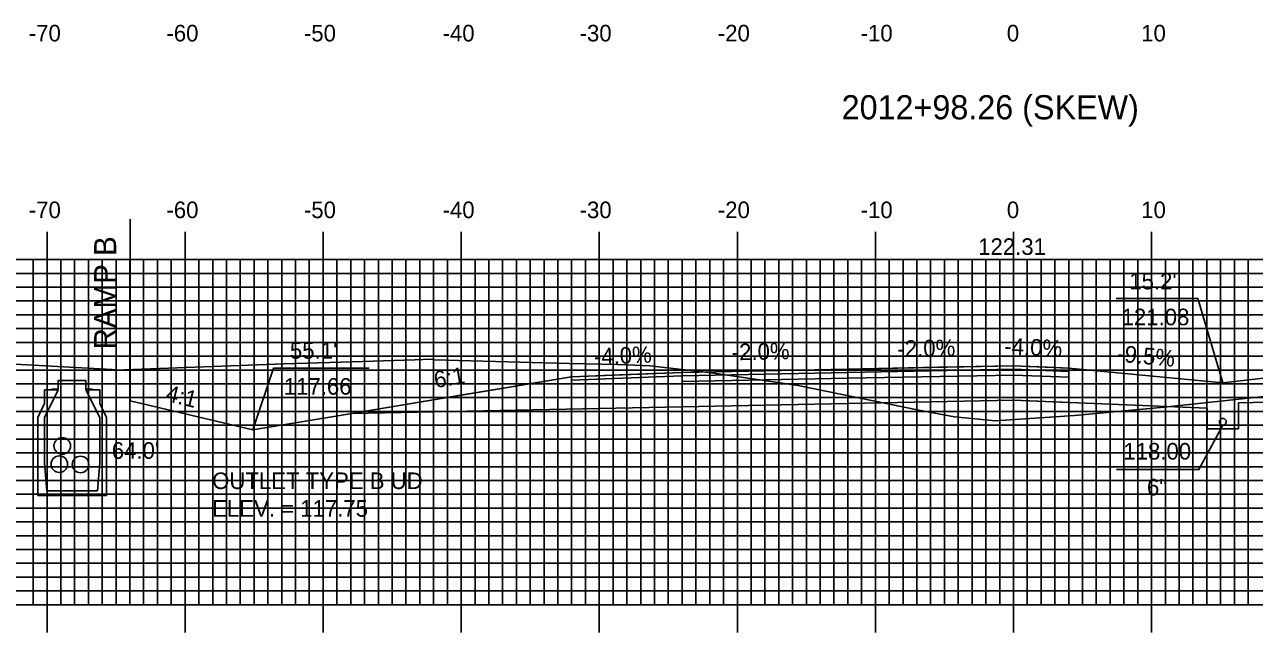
# Model space of a CAD drawing. Extents: x 853894 to 854237, y 366605 to 366825.
# Drawn here: x 853987.9 to 854077, y 366706.1 to 366750.1 of the extents above; entities that cross this region are included whole.
import ezdxf

# ---------------------------------------------------------------- set-up
doc = ezdxf.new("R2010")
doc.units = 0
for name, color, linetype in [('ANNOTATION', 7, 'Continuous'), ('D_Roadway_Centerline', 7, 'Continuous'), ('D_Roadway_Centerline_Text', 7, 'Continuous'), ('D_Roadway_Edge_Shoulder', 7, 'Continuous'), ('D_Roadway_Edge_TW', 7, 'Continuous'), ('D_Roadway_Pavement', 7, 'Continuous'), ('D_Roadway_SubGrade', 7, 'Continuous'), ('D_Text_Standard', 7, 'Continuous'), ('H_V ANNOTATION', 7, 'Continuous'), ('M_Roadway_Centerline', 7, 'Continuous'), ('MAJOR', 7, 'Continuous'), ('MINOR', 7, 'Continuous'), ('PDRAIN', 7, 'Continuous'), ('S_Drainage_CB', 7, 'Continuous'), ('S_Drainage_Invert', 7, 'Continuous'), ('S_Roadway_Centerline', 7, 'Continuous')]:
    doc.layers.add(name, color=color, linetype=linetype)

msp = doc.modelspace()

# ---------------------------------------------------------------- linework, layer by layer
at = {"layer": 'ANNOTATION'}
for points in [[(854066.975, 366730.223), (854072.876, 366730.223), (854074.694, 366724.138)], [(854012.87, 366725.196), (854005.941, 366725.196), (854004.439, 366720.713)], [(854066.993, 366717.845), (854072.964, 366717.845), (854074.694, 366721.055)]]:
    msp.add_lwpolyline(points, dxfattribs=at)
at = {"layer": 'D_Roadway_Centerline'}
for p, q in [((854059.53, 366722.861), (854073.569, 366722.3)), ((854084.707, 366722.859), (854075.819, 366722.677))]:
    msp.add_line(p, q, dxfattribs=at)
for points in [[(854010.439, 366721.713), (854010.445, 366721.714), (854020.081, 366723.32), (854027.53, 366724.561), (854027.532, 366724.561), (854031.021, 366724.701), (854035.528, 366724.881), (854035.53, 366724.881), (854047.525, 366725.121), (854047.53, 366725.121), (854054.093, 366725.252), (854059.53, 366725.361), (854062.579, 366725.239), (854063.53, 366725.201), (854063.531, 366725.201), (854074.694, 366724.138)], [(854063.53, 366725.201), (854074.694, 366724.138)], [(854074.694, 366724.138), (854077.41, 366724.448), (854084.707, 366725.279)]]:
    msp.add_lwpolyline(points, dxfattribs=at)
at = {"layer": 'D_Roadway_Edge_Shoulder'}
for points in [[(854035.53, 366724.881), (854027.53, 366724.561), (854027.53, 366724.311), (854035.53, 366724.631)], [(854059.53, 366725.361), (854063.53, 366725.201), (854063.53, 366724.951), (854059.53, 366725.111)]]:
    msp.add_lwpolyline(points, close=True, dxfattribs=at)
at = {"layer": 'D_Roadway_Edge_TW'}
for points in [[(854047.53, 366725.121), (854035.53, 366724.881), (854035.53, 366724.631), (854047.53, 366724.871)], [(854059.53, 366725.361), (854047.53, 366725.121), (854047.53, 366724.871), (854059.53, 366725.111)]]:
    msp.add_lwpolyline(points, close=True, dxfattribs=at)
at = {"layer": 'D_Roadway_Pavement'}
for points in [[(854047.53, 366724.871), (854035.53, 366724.631), (854035.53, 366724.214), (854047.53, 366724.454)], [(854059.53, 366725.111), (854047.53, 366724.871), (854047.53, 366724.454), (854059.53, 366724.694)], [(854059.53, 366725.111), (854063.53, 366724.951), (854063.53, 366724.534), (854059.53, 366724.694)], [(854035.53, 366724.631), (854035.53, 366724.214), (854035.53, 366724.214)]]:
    msp.add_lwpolyline(points, close=True, dxfattribs=at)
msp.add_lwpolyline([(854047.53, 366724.871), (854047.53, 366724.454)], dxfattribs=at)
at = {"layer": 'D_Roadway_SubGrade'}
msp.add_line((853995.55, 366735.973), (853995.55, 366722.827), dxfattribs=at)
for points in [[(854059.53, 366724.694), (854063.53, 366724.534), (854063.53, 366724.951), (854063.53, 366725.201), (854063.53, 366722.701), (854059.53, 366722.861)], [(854035.53, 366724.214), (854035.53, 366724.214), (854035.53, 366724.631), (854027.53, 366724.311), (854027.53, 366724.561), (854011.576, 366721.902), (854035.53, 366722.381)], [(854047.53, 366724.454), (854035.53, 366724.214), (854035.53, 366722.381), (854047.53, 366722.621)], [(854059.53, 366724.694), (854047.53, 366724.454), (854047.53, 366722.621), (854059.53, 366722.861)]]:
    msp.add_lwpolyline(points, close=True, dxfattribs=at)
msp.add_lwpolyline([(854010.439, 366721.713), (854004.439, 366720.713), (853995.55, 366722.827)], dxfattribs=at)
at = {"layer": 'MAJOR'}
for p, q in [((853989.53, 366735.059), (853989.53, 366733.055)), ((853999.53, 366735.059), (853999.53, 366733.055)), ((854009.53, 366735.059), (854009.53, 366733.055)), ((854019.53, 366735.059), (854019.53, 366733.055)), ((854029.53, 366735.059), (854029.53, 366733.055)), ((854039.53, 366735.059), (854039.53, 366733.055)), ((854049.53, 366735.059), (854049.53, 366733.055)), ((854059.53, 366735.059), (854059.53, 366733.055)), ((854069.53, 366735.059), (854069.53, 366733.055)), ((853919.53, 366733.055), (854199.53, 366733.055)), ((853919.53, 366733.055), (854199.53, 366733.055)), ((853989.53, 366708.055), (853989.53, 366733.055)), ((853999.53, 366708.055), (853999.53, 366733.055)), ((854009.53, 366708.055), (854009.53, 366733.055)), ((854019.53, 366708.055), (854019.53, 366733.055)), ((854029.53, 366708.055), (854029.53, 366733.055)), ((854039.53, 366708.055), (854039.53, 366733.055)), ((854049.53, 366708.055), (854049.53, 366733.055)), ((854059.53, 366708.055), (854059.53, 366733.055)), ((854069.53, 366708.055), (854069.53, 366733.055)), ((853919.53, 366728.055), (854199.53, 366728.055)), ((853919.53, 366723.055), (854199.53, 366723.055)), ((853919.53, 366718.055), (854199.53, 366718.055)), ((853919.53, 366713.055), (854199.53, 366713.055)), ((853919.53, 366708.055), (854199.53, 366708.055)), ((853919.53, 366708.055), (854199.53, 366708.055)), ((853989.53, 366706.051), (853989.53, 366708.055)), ((853999.53, 366706.051), (853999.53, 366708.055)), ((854009.53, 366706.051), (854009.53, 366708.055)), ((854019.53, 366706.051), (854019.53, 366708.055)), ((854029.53, 366706.051), (854029.53, 366708.055)), ((854039.53, 366706.051), (854039.53, 366708.055)), ((854049.53, 366706.051), (854049.53, 366708.055)), ((854059.53, 366706.051), (854059.53, 366708.055)), ((854069.53, 366706.051), (854069.53, 366708.055))]:
    msp.add_line(p, q, dxfattribs=at)
at = {"layer": 'MINOR'}
for p, q in [((853988.53, 366708.055), (853988.53, 366733.055)), ((853990.53, 366708.055), (853990.53, 366733.055)), ((853991.53, 366708.055), (853991.53, 366733.055)), ((853992.53, 366708.055), (853992.53, 366733.055)), ((853993.53, 366708.055), (853993.53, 366733.055)), ((853994.53, 366708.055), (853994.53, 366733.055)), ((853995.53, 366708.055), (853995.53, 366733.055)), ((853996.53, 366708.055), (853996.53, 366733.055)), ((853997.53, 366708.055), (853997.53, 366733.055)), ((853998.53, 366708.055), (853998.53, 366733.055)), ((854000.53, 366708.055), (854000.53, 366733.055)), ((854001.53, 366708.055), (854001.53, 366733.055)), ((854002.53, 366708.055), (854002.53, 366733.055)), ((854003.53, 366708.055), (854003.53, 366733.055)), ((854004.53, 366708.055), (854004.53, 366733.055)), ((854005.53, 366708.055), (854005.53, 366733.055)), ((854006.53, 366708.055), (854006.53, 366733.055)), ((854007.53, 366708.055), (854007.53, 366733.055)), ((854008.53, 366708.055), (854008.53, 366733.055)), ((854010.53, 366708.055), (854010.53, 366733.055)), ((854011.53, 366708.055), (854011.53, 366733.055)), ((854012.53, 366708.055), (854012.53, 366733.055)), ((854013.53, 366708.055), (854013.53, 366733.055)), ((854014.53, 366708.055), (854014.53, 366733.055)), ((854015.53, 366708.055), (854015.53, 366733.055)), ((854016.53, 366708.055), (854016.53, 366733.055)), ((854017.53, 366708.055), (854017.53, 366733.055)), ((854018.53, 366708.055), (854018.53, 366733.055)), ((854020.53, 366708.055), (854020.53, 366733.055)), ((854021.53, 366708.055), (854021.53, 366733.055)), ((854022.53, 366708.055), (854022.53, 366733.055)), ((854023.53, 366708.055), (854023.53, 366733.055)), ((854024.53, 366708.055), (854024.53, 366733.055)), ((854025.53, 366708.055), (854025.53, 366733.055)), ((854026.53, 366708.055), (854026.53, 366733.055)), ((854027.53, 366708.055), (854027.53, 366733.055)), ((854028.53, 366708.055), (854028.53, 366733.055)), ((854030.53, 366708.055), (854030.53, 366733.055)), ((854031.53, 366708.055), (854031.53, 366733.055)), ((854032.53, 366708.055), (854032.53, 366733.055)), ((854033.53, 366708.055), (854033.53, 366733.055)), ((854034.53, 366708.055), (854034.53, 366733.055)), ((854035.53, 366708.055), (854035.53, 366733.055)), ((854036.53, 366708.055), (854036.53, 366733.055)), ((854037.53, 366708.055), (854037.53, 366733.055)), ((854038.53, 366708.055), (854038.53, 366733.055)), ((854040.53, 366708.055), (854040.53, 366733.055)), ((854041.53, 366708.055), (854041.53, 366733.055)), ((854042.53, 366708.055), (854042.53, 366733.055)), ((854043.53, 366708.055), (854043.53, 366733.055)), ((854044.53, 366708.055), (854044.53, 366733.055)), ((854045.53, 366708.055), (854045.53, 366733.055)), ((854046.53, 366708.055), (854046.53, 366733.055)), ((854047.53, 366708.055), (854047.53, 366733.055)), ((854048.53, 366708.055), (854048.53, 366733.055)), ((854050.53, 366708.055), (854050.53, 366733.055)), ((854051.53, 366708.055), (854051.53, 366733.055)), ((854052.53, 366708.055), (854052.53, 366733.055)), ((854053.53, 366708.055), (854053.53, 366733.055)), ((854054.53, 366708.055), (854054.53, 366733.055)), ((854055.53, 366708.055), (854055.53, 366733.055)), ((854056.53, 366708.055), (854056.53, 366733.055)), ((854057.53, 366708.055), (854057.53, 366733.055)), ((854058.53, 366708.055), (854058.53, 366733.055)), ((854060.53, 366708.055), (854060.53, 366733.055)), ((854061.53, 366708.055), (854061.53, 366733.055)), ((854062.53, 366708.055), (854062.53, 366733.055)), ((854063.53, 366708.055), (854063.53, 366733.055)), ((854064.53, 366708.055), (854064.53, 366733.055)), ((854065.53, 366708.055), (854065.53, 366733.055)), ((854066.53, 366708.055), (854066.53, 366733.055)), ((854067.53, 366708.055), (854067.53, 366733.055)), ((854068.53, 366708.055), (854068.53, 366733.055)), ((854070.53, 366708.055), (854070.53, 366733.055)), ((854071.53, 366708.055), (854071.53, 366733.055)), ((854072.53, 366708.055), (854072.53, 366733.055)), ((854073.53, 366708.055), (854073.53, 366733.055)), ((854074.53, 366708.055), (854074.53, 366733.055)), ((854075.53, 366708.055), (854075.53, 366733.055)), ((854076.53, 366708.055), (854076.53, 366733.055)), ((853919.53, 366732.055), (854199.53, 366732.055)), ((853919.53, 366731.055), (854199.53, 366731.055)), ((853919.53, 366730.055), (854199.53, 366730.055)), ((853919.53, 366729.055), (854199.53, 366729.055)), ((853919.53, 366727.055), (854199.53, 366727.055)), ((853919.53, 366726.055), (854199.53, 366726.055)), ((853919.53, 366725.055), (854199.53, 366725.055)), ((853919.53, 366724.055), (854199.53, 366724.055)), ((853919.53, 366722.055), (854199.53, 366722.055)), ((853919.53, 366721.055), (854199.53, 366721.055)), ((853919.53, 366720.055), (854199.53, 366720.055)), ((853919.53, 366719.055), (854199.53, 366719.055)), ((853919.53, 366717.055), (854199.53, 366717.055)), ((853919.53, 366716.055), (854199.53, 366716.055)), ((853919.53, 366715.055), (854199.53, 366715.055)), ((853919.53, 366714.055), (854199.53, 366714.055)), ((853919.53, 366712.055), (854199.53, 366712.055)), ((853919.53, 366711.055), (854199.53, 366711.055)), ((853919.53, 366710.055), (854199.53, 366710.055)), ((853919.53, 366709.055), (854199.53, 366709.055))]:
    msp.add_line(p, q, dxfattribs=at)
at = {"layer": 'PDRAIN'}
msp.add_lwpolyline([(854073.569, 366722.3), (854073.569, 366720.805), (854075.819, 366720.805), (854075.819, 366722.677)], dxfattribs=at)
msp.add_circle((854074.694, 366721.305), 0.25, dxfattribs=at)
at = {"layer": 'S_Drainage_CB'}
for p, q in [((853990.336, 366723.621), (853989.352, 366723.621)), ((853989.352, 366723.621), (853989.352, 366722.637)), ((853989.352, 366721.62), (853990.336, 366723.621)), ((853993.354, 366723.621), (853992.337, 366723.621)), ((853992.337, 366723.621), (853993.354, 366721.62)), ((853993.354, 366722.637), (853993.354, 366723.621)), ((853989.352, 366722.637), (853988.859, 366721.62)), ((853993.846, 366721.62), (853993.354, 366722.637)), ((853988.859, 366721.62), (853988.859, 366715.977)), ((853989.352, 366718.306), (853989.352, 366721.62)), ((853993.354, 366721.62), (853993.354, 366718.306)), ((853993.846, 366715.977), (853993.846, 366721.62)), ((853989.516, 366716.305), (853989.352, 366718.306)), ((853993.354, 366718.306), (853993.19, 366716.305)), ((853988.859, 366715.977), (853993.846, 366715.977)), ((853993.19, 366716.305), (853989.516, 366716.305))]:
    msp.add_line(p, q, dxfattribs=at)
msp.add_lwpolyline([(853992.829, 366723.663), (853992.337, 366723.663), (853992.337, 366724.286), (853990.336, 366724.286), (853990.336, 366723.663), (853989.844, 366723.663)], dxfattribs=at)
at = {"layer": 'S_Drainage_Invert'}
for centre in [(853990.635, 366719.555), (853990.422, 366718.238), (853991.96, 366718.215)]:
    msp.add_circle(centre, 0.6, dxfattribs=at)
at = {"layer": 'S_Roadway_Centerline'}
msp.add_lwpolyline([(853982.751, 366725.716), (853994.256, 366725.083), (853994.762, 366725.055), (853994.824, 366725.048), (853994.842, 366725.046), (853994.866, 366725.043), (853995.092, 366725.058), (854006.718, 366725.515), (854011.623, 366725.651), (854016.178, 366725.798), (854017.347, 366725.844), (854017.541, 366725.781), (854027.343, 366725.532), (854030.858, 366725.464), (854031.515, 366725.428), (854033.182, 366725.357), (854037.656, 366724.854), (854043.942, 366723.934), (854052.687, 366722.153), (854055.268, 366721.674), (854058.217, 366721.367), (854063.959, 366721.76), (854070.451, 366722.355), (854086.689, 366724.098)], dxfattribs=at)

# ---------------------------------------------------------------- texts
at = {"layer": 'ANNOTATION'}
for s, height, rotation, p in [('RAMP B', 1.6, 90, (853994.542, 366726.541)), ('-4.0%', 1.2, 2.29058, (854029.162, 366725.428)), ('-2.0%', 1.2, 1.14576, (854039.134, 366725.754)), ('-2.0%', 1.2, 1.14573, (854051.136, 366725.994)), ('-4.0%', 1.2, 357.709, (854058.847, 366726.19)), ('-9.5%', 1.2, 354.56097, (854067.001, 366725.68)), ('6:1', 1.2, 9.46088, (854017.663, 366723.745)), ('4:1', 1.2, 346.18377, (853998.062, 366722.831)), ('118.00', 1.2, 360, (854067.486, 366718.571)), ('6"', 1.2, 360, (854069.198, 366715.971))]:
    msp.add_text(s, height=height, rotation=rotation, dxfattribs=at).set_placement(p)
for s, p in [("15.2' ", (854067.917, 366730.897)), ('121.08', (854067.361, 366728.297)), ("55.1'", (854007.122, 366725.87)), ('117.66', (854006.678, 366723.27)), ('OUTLET TYPE B UD', (854001.492, 366716.435)), ('ELEV. = 117.75', (854001.492, 366714.431))]:
    msp.add_text(s, height=1.2, dxfattribs=at).set_placement(p)
at = {"layer": 'D_Roadway_Centerline_Text'}
msp.add_text('122.31', height=1.2, dxfattribs=at).set_placement((854056.972, 366733.393))
at = {"layer": 'D_Text_Standard'}
msp.add_text("64.0'", height=1.2, dxfattribs=at).set_placement((853994.221, 366718.625))
at = {"layer": 'H_V ANNOTATION'}
for s, height, p in [('-70', 1.2, (853988.213, 366748.855)), ('-60', 1.2, (853998.181, 366748.855)), ('-50', 1.2, (854008.138, 366748.855)), ('-40', 1.2, (854018.181, 366748.855)), ('-30', 1.2, (854028.106, 366748.855)), ('-20', 1.2, (854038.117, 366748.855)), ('-10', 1.2, (854048.46, 366748.855)), ('0', 1.2, (854059.048, 366748.855)), ('10', 1.2, (854068.781, 366748.855)), ('2012+98.26 (SKEW)', 1.74996, (854047.084, 366743.211)), ('-70', 1.2, (853988.213, 366736.055)), ('-60', 1.2, (853998.181, 366736.055)), ('-50', 1.2, (854008.138, 366736.055)), ('-40', 1.2, (854018.181, 366736.055)), ('-30', 1.2, (854028.106, 366736.055)), ('-20', 1.2, (854038.117, 366736.055)), ('-10', 1.2, (854048.46, 366736.055)), ('0', 1.2, (854059.048, 366736.055)), ('10', 1.2, (854068.781, 366736.055))]:
    msp.add_text(s, height=height, dxfattribs=at).set_placement(p)
at = {"layer": 'M_Roadway_Centerline'}
for s, p in [('C', (854017.342, 366725.844)), ('L', (854017.347, 366725.836))]:
    msp.add_text(s, height=0.0146, dxfattribs=at).set_placement(p)

doc.saveas('drawing.dxf')
